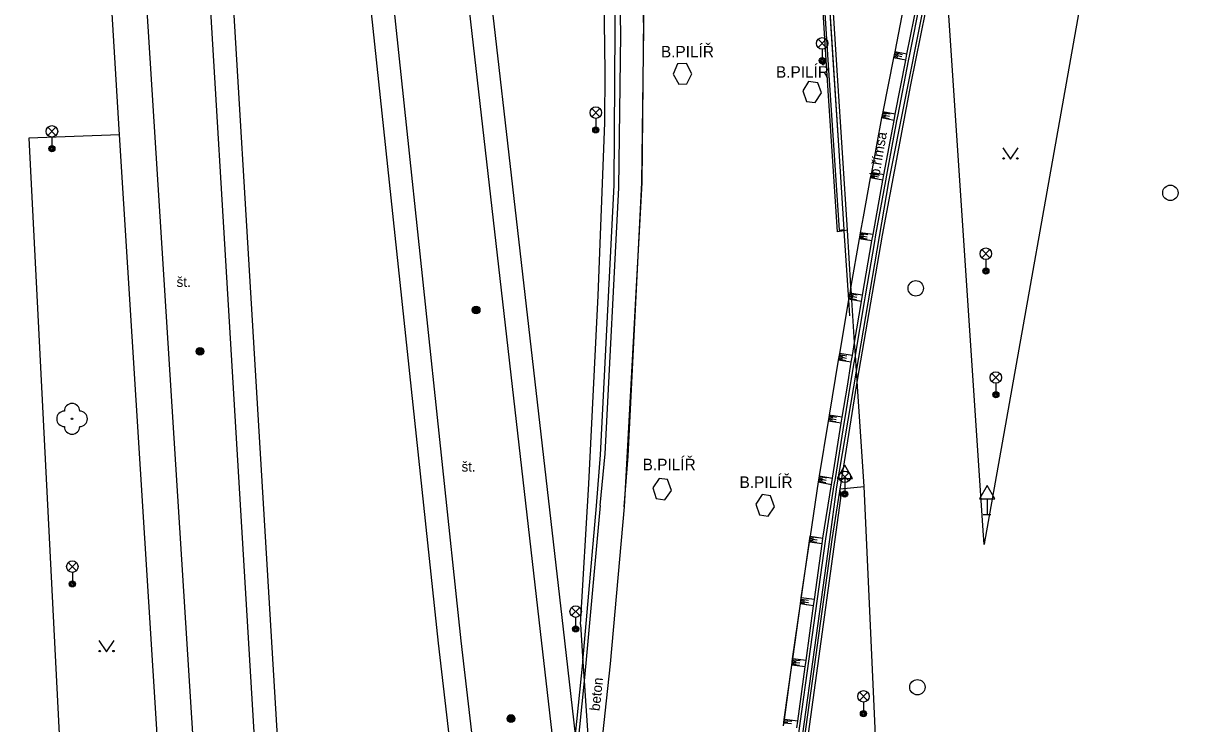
# Model space of a CAD drawing. Extents: x -599951 to -598963, y -1164095 to -1162939.
# Drawn here: x -599212.4 to -599136.9, y -1163692.1 to -1163646.4 of the extents above; entities that cross this region are included whole.
import ezdxf

# ---------------------------------------------------------------- set-up
doc = ezdxf.new("R2010")
doc.units = 0
for name, color, linetype in [('Level 10', 7, 'Continuous'), ('Level 11', 7, 'Continuous'), ('Level 13', 7, 'Continuous'), ('Level 15', 7, 'Continuous'), ('Level 22', 7, 'Continuous'), ('Level 25', 7, 'Continuous'), ('Level 27', 7, 'Continuous'), ('Level 33', 7, 'Continuous'), ('Level 34', 7, 'Continuous'), ('Level 36', 7, 'Continuous'), ('Level 40', 7, 'Continuous'), ('Level 41', 7, 'Continuous'), ('Level 9', 7, 'Continuous')]:
    doc.layers.add(name, color=color, linetype=linetype)

msp = doc.modelspace()

# ---------------------------------------------------------------- linework, layer by layer
at = {"layer": 'Level 10'}
for points in [[(-599097.7, -1163496.33), (-599101.18, -1163504.5), (-599105.65, -1163515.42), (-599108.56, -1163522.79), (-599112.67, -1163533.66), (-599115.92, -1163542.44), (-599118.17, -1163548.8), (-599119.97, -1163554.03), (-599122.34, -1163561.22), (-599124.91, -1163569.39), (-599126.83, -1163575.79), (-599128.48, -1163581.37), (-599129.72, -1163585.79), (-599133.24, -1163599), (-599135.77, -1163608.36), (-599139.28, -1163623.33), (-599143.16, -1163642.62), (-599149.778, -1163679.861), (-599149.81, -1163680.07), (-599149.87, -1163680.38)], [(-599158.77, -1163659.9), (-599159.42, -1163649.83), (-599161.31, -1163620.29)], [(-599149.87, -1163680.38), (-599149.89, -1163680.05), (-599149.909, -1163679.799), (-599152.24, -1163644.59), (-599152.53, -1163640.01)], [(-599155, -1163644.76), (-599155.67, -1163648.28)], [(-599172.15, -1163656.79), (-599172.03, -1163646.75), (-599172.06, -1163645.35)], [(-599155.76, -1163648.67), (-599156.47, -1163652.19)], [(-599155.67, -1163648.28), (-599155.76, -1163648.67)], [(-599156.55, -1163652.59), (-599157.2, -1163656.14)], [(-599156.47, -1163652.19), (-599156.55, -1163652.59)], [(-599157.28, -1163656.5), (-599157.75, -1163659.03), (-599157.93, -1163660.07)], [(-599157.2, -1163656.14), (-599157.28, -1163656.5)], [(-599173.3, -1163677.93), (-599173.05, -1163674.62), (-599172.15, -1163656.79)], [(-599158.54, -1163663.54), (-599158.77, -1163659.9)], [(-599157.93, -1163660.07), (-599158, -1163660.46)], [(-599158, -1163660.46), (-599158.54, -1163663.54)], [(-599158.62, -1163664), (-599158.69, -1163664.4)], [(-599158.54, -1163663.54), (-599158.62, -1163664)], [(-599158.51, -1163664.02), (-599158.54, -1163663.54)], [(-599158.48, -1163664.44), (-599158.51, -1163664.02)], [(-599158.7, -1163664.44), (-599159.28, -1163667.93)], [(-599158.69, -1163664.4), (-599158.7, -1163664.44)], [(-599158.3, -1163667.21), (-599158.48, -1163664.44)], [(-599158.24, -1163668.05), (-599158.3, -1163667.21)], [(-599159.37, -1163668.37), (-599159.95, -1163671.95)], [(-599159.28, -1163667.93), (-599159.37, -1163668.37)], [(-599158.17, -1163669.09), (-599158.24, -1163668.05)], [(-599158.13, -1163669.68), (-599158.17, -1163669.09)], [(-599158.13, -1163669.76), (-599158.13, -1163669.68)], [(-599157.68, -1163676.6), (-599158.13, -1163669.76)], [(-599160.02, -1163672.35), (-599160.6, -1163675.9)], [(-599159.95, -1163671.95), (-599160.02, -1163672.35)], [(-599160.6, -1163675.9), (-599160.68, -1163676.3)], [(-599162.85, -1163820.04), (-599162.62, -1163815.71), (-599158.85, -1163766.66), (-599157.06, -1163745.81), (-599155.93, -1163733.73), (-599156.18, -1163710.45), (-599156.98, -1163691.85), (-599157.68, -1163676.6)], [(-599160.68, -1163676.3), (-599161.2, -1163679.83)], [(-599161.24, -1163680.23), (-599161.2, -1163679.83)], [(-599161.77, -1163683.84), (-599161.24, -1163680.23)], [(-599162.34, -1163687.82), (-599161.83, -1163684.25)], [(-599161.83, -1163684.25), (-599161.77, -1163683.84)], [(-599162.88, -1163691.77), (-599162.39, -1163688.23)], [(-599162.39, -1163688.23), (-599162.34, -1163687.82)], [(-599162.92, -1163692.19), (-599162.88, -1163691.77)]]:
    msp.add_lwpolyline(points, dxfattribs=at)
at = {"layer": 'Level 11'}
for points in [[(-599206.17, -1163653.7), (-599209.8, -1163593.38), (-599213.54, -1163512.63), (-599213.84, -1163496.33), (-599214.13, -1163485.25)], [(-599189.36, -1163823.61), (-599189.69, -1163796.53), (-599191.33, -1163764.7), (-599192.09, -1163753.19), (-599195.83, -1163693.59), (-599200.49, -1163615.9), (-599203.73, -1163564.1), (-599205.07, -1163538.8), (-599205.4, -1163502.64)], [(-599205.4, -1163502.64), (-599201.6, -1163538.16), (-599192.85, -1163616.71), (-599185.42, -1163686.81), (-599180.49, -1163729.19)], [(-599176.47, -1163692.74), (-599177.25, -1163685.88), (-599185.21, -1163616.31), (-599194.22, -1163537.61)], [(-599176.14, -1163685.58), (-599175.61, -1163676.43), (-599174.99, -1163664.15), (-599174.55, -1163652.9), (-599174.53, -1163649.56), (-599174.7, -1163638.37), (-599174.9, -1163629.3), (-599175.26, -1163620.59), (-599175.8, -1163615.25), (-599176.49, -1163610.52), (-599177.6, -1163604.96)], [(-599175.11, -1163677.86), (-599174.84, -1163674.53), (-599173.95, -1163656.98), (-599173.87, -1163643.39), (-599174.3, -1163631.07), (-599175.13, -1163619.77), (-599176.19, -1163608.83), (-599176.71, -1163604.87)], [(-599161.5, -1163621.13), (-599159.68, -1163649.46), (-599159.35, -1163654.39)], [(-599158.99, -1163659.94), (-599159.42, -1163660.02), (-599160.1, -1163649.5), (-599161.81, -1163622.49)], [(-599161.75, -1163622.22), (-599160, -1163649.48), (-599159.31, -1163659.91)], [(-599158.24, -1163668.05), (-599157.66, -1163664.57), (-599157.59, -1163664.17), (-599156.98, -1163660.63), (-599156.91, -1163660.21), (-599156.27, -1163656.69), (-599156.2, -1163656.33), (-599155.54, -1163652.79), (-599155.46, -1163652.39), (-599154.78, -1163648.87), (-599154.71, -1163648.47), (-599154, -1163644.96), (-599153.91, -1163644.52), (-599153.19, -1163641.02), (-599153.1, -1163640.6), (-599152.62, -1163638.35)], [(-599152.53, -1163640.01), (-599153.04, -1163642.39), (-599154.67, -1163650.43), (-599156.51, -1163660.23), (-599158.13, -1163669.68)], [(-599154.9, -1163648.43), (-599154.19, -1163644.92)], [(-599154.97, -1163648.83), (-599155.76, -1163648.67)], [(-599154.9, -1163648.43), (-599155.67, -1163648.28)], [(-599155.65, -1163652.35), (-599154.97, -1163648.83)], [(-599154.97, -1163648.83), (-599154.9, -1163648.43)], [(-599169.25, -1163649.05), (-599169.83, -1163649.06), (-599170.12, -1163649.74), (-599169.75, -1163650.39), (-599169.22, -1163650.38), (-599168.9, -1163649.72), (-599169.25, -1163649.05)], [(-599160.69, -1163650.31), (-599161.29, -1163650.22), (-599161.68, -1163650.83), (-599161.43, -1163651.53), (-599160.87, -1163651.58), (-599160.46, -1163650.96), (-599160.69, -1163650.31)], [(-599155.73, -1163652.75), (-599156.55, -1163652.59)], [(-599155.65, -1163652.35), (-599156.47, -1163652.19)], [(-599156.39, -1163656.29), (-599155.73, -1163652.75)], [(-599155.73, -1163652.75), (-599155.65, -1163652.35)], [(-599206.17, -1163653.7), (-599212.07, -1163653.92), (-599206.95, -1163754.57), (-599203.73, -1163825.91)], [(-599206.17, -1163653.7), (-599212.07, -1163653.92), (-599206.95, -1163754.57), (-599203.73, -1163825.91)], [(-599197.62, -1163823.43), (-599198.47, -1163776.3), (-599199.87, -1163753.93), (-599206.17, -1163653.7)], [(-599159.35, -1163654.39), (-599158.99, -1163659.85)], [(-599156.46, -1163656.65), (-599157.28, -1163656.5)], [(-599156.39, -1163656.29), (-599157.2, -1163656.14)], [(-599156.46, -1163656.65), (-599156.39, -1163656.29)], [(-599157.1, -1163660.18), (-599156.46, -1163656.65)], [(-599159.31, -1163659.91), (-599159, -1163659.85)], [(-599159, -1163659.85), (-599158.99, -1163659.85)], [(-599158.77, -1163659.9), (-599158.99, -1163659.94)], [(-599157.1, -1163660.18), (-599157.93, -1163660.07)], [(-599157.17, -1163660.6), (-599157.1, -1163660.18)], [(-599157.17, -1163660.6), (-599158, -1163660.46)], [(-599157.78, -1163664.14), (-599157.17, -1163660.6)], [(-599158.51, -1163664.02), (-599158.62, -1163664)], [(-599157.78, -1163664.14), (-599158.51, -1163664.02)], [(-599158.48, -1163664.44), (-599158.69, -1163664.4)], [(-599157.85, -1163664.54), (-599158.48, -1163664.44)], [(-599158.3, -1163667.21), (-599157.85, -1163664.54)], [(-599157.85, -1163664.54), (-599157.78, -1163664.14)], [(-599158.44, -1163668.07), (-599158.3, -1163667.21)], [(-599160.17, -1163680.01), (-599159.62, -1163676.49), (-599159.55, -1163676.08), (-599158.98, -1163672.5), (-599158.91, -1163672.12), (-599158.58, -1163670.09), (-599158.33, -1163668.54), (-599158.25, -1163668.1), (-599158.24, -1163668.05)], [(-599158.52, -1163668.51), (-599159.37, -1163668.37)], [(-599158.44, -1163668.07), (-599159.28, -1163667.93)], [(-599159.1, -1163672.09), (-599158.77, -1163670.06), (-599158.52, -1163668.51)], [(-599158.52, -1163668.51), (-599158.44, -1163668.07)], [(-599158.13, -1163669.68), (-599158.27, -1163670.47), (-599159.78, -1163680.04)], [(-599159.17, -1163672.47), (-599160.02, -1163672.35)], [(-599159.1, -1163672.09), (-599159.95, -1163671.95)], [(-599159.17, -1163672.47), (-599159.1, -1163672.09)], [(-599159.74, -1163676.05), (-599159.17, -1163672.47)], [(-599170.48, -1163676.15), (-599171.03, -1163676.07), (-599171.44, -1163676.68), (-599171.22, -1163677.39), (-599170.65, -1163677.46), (-599170.23, -1163676.86), (-599170.48, -1163676.15)], [(-599160.6, -1163675.9), (-599159.74, -1163676.05)], [(-599159.81, -1163676.46), (-599159.74, -1163676.05)], [(-599167.61, -1163750.42), (-599167.49, -1163749.46), (-599165.73, -1163731.33), (-599162.94, -1163704.73), (-599159.2, -1163677.36), (-599159.24, -1163676.76), (-599157.68, -1163676.6)], [(-599160.68, -1163676.3), (-599159.81, -1163676.46)], [(-599160.36, -1163679.96), (-599159.81, -1163676.46)], [(-599163.77, -1163677.2), (-599164.31, -1163677.12), (-599164.72, -1163677.74), (-599164.5, -1163678.45), (-599163.93, -1163678.52), (-599163.51, -1163677.92), (-599163.77, -1163677.2)], [(-599175.99, -1163688), (-599175.11, -1163677.86)], [(-599161.2, -1163679.83), (-599160.36, -1163679.96)], [(-599160.41, -1163680.34), (-599160.36, -1163679.96)], [(-599168.09, -1163750.4), (-599167.18, -1163739.59), (-599165.19, -1163719.7), (-599162.93, -1163699.85), (-599160.17, -1163680.01)], [(-599159.78, -1163680.04), (-599162.54, -1163699.92), (-599164.82, -1163719.73), (-599166.77, -1163739.69), (-599167.68, -1163750.42)], [(-599160.41, -1163680.34), (-599161.24, -1163680.23)], [(-599160.91, -1163683.96), (-599160.41, -1163680.34)], [(-599160.97, -1163684.37), (-599161.83, -1163684.25)], [(-599160.91, -1163683.96), (-599161.77, -1163683.84)], [(-599161.46, -1163687.94), (-599160.97, -1163684.37)], [(-599160.97, -1163684.37), (-599160.91, -1163683.96)], [(-599176.14, -1163685.58), (-599175.99, -1163688)], [(-599176.47, -1163692.74), (-599176, -1163688.08), (-599175.99, -1163688)], [(-599175.99, -1163688), (-599175.91, -1163689.25)], [(-599162.38, -1163688.23), (-599162.39, -1163688.23)], [(-599161.52, -1163688.35), (-599162.38, -1163688.23)], [(-599162.32, -1163687.82), (-599162.34, -1163687.82)], [(-599161.46, -1163687.94), (-599162.32, -1163687.82)], [(-599161.52, -1163688.35), (-599161.46, -1163687.94)], [(-599162, -1163691.89), (-599161.52, -1163688.35)], [(-599175.91, -1163689.25), (-599175.31, -1163698.01)], [(-599162.86, -1163691.77), (-599162.88, -1163691.77)], [(-599162, -1163691.89), (-599162.86, -1163691.77)], [(-599162.06, -1163692.31), (-599162, -1163691.89)]]:
    msp.add_lwpolyline(points, dxfattribs=at)
at = {"layer": 'Level 13'}
for points in [[(-599191.12, -1163824.29), (-599191.19, -1163796.58), (-599192.83, -1163764.79), (-599193.59, -1163753.29), (-599197.33, -1163693.68), (-599201.99, -1163615.99), (-599205.23, -1163564.19), (-599206.57, -1163538.85), (-599206.81, -1163512.73), (-599206.44, -1163495.99), (-599204.7, -1163459.51)], [(-599191.12, -1163824.29), (-599191.19, -1163796.58), (-599192.83, -1163764.79), (-599193.59, -1163753.29), (-599197.33, -1163693.68), (-599201.99, -1163615.99), (-599205.23, -1163564.19), (-599206.57, -1163538.85), (-599206.81, -1163512.73), (-599206.44, -1163495.99), (-599204.7, -1163459.51)], [(-599177.23, -1163699.28), (-599178.74, -1163686.05), (-599186.7, -1163616.48), (-599195.66, -1163537.6), (-599200.41, -1163495.95), (-599204.7, -1163459.51)], [(-599208.62, -1163460.66), (-599210.47, -1163495.7), (-599211.19, -1163512.78), (-599210.75, -1163539.06), (-599209.44, -1163564.41), (-599206.24, -1163616.03), (-599201.34, -1163693.72), (-599197.51, -1163753.71), (-599196.88, -1163764.86), (-599195.14, -1163797.79), (-599195.48, -1163824.85)], [(-599208.62, -1163460.66), (-599210.47, -1163495.7), (-599211.19, -1163512.78), (-599210.75, -1163539.06), (-599209.44, -1163564.41), (-599206.24, -1163616.03), (-599201.34, -1163693.72), (-599197.51, -1163753.71), (-599196.88, -1163764.86), (-599195.14, -1163797.79), (-599195.48, -1163824.85)], [(-599208.62, -1163460.66), (-599204.63, -1163495.77), (-599200.11, -1163538), (-599191.36, -1163616.55), (-599183.93, -1163686.65), (-599179.8, -1163722.27)]]:
    msp.add_lwpolyline(points, dxfattribs=at)
at = {"layer": 'Level 15'}
for points in [[(-599155.75, -1163648.63), (-599155.26, -1163648.74)], [(-599155.73, -1163648.56), (-599155.49, -1163648.61)], [(-599155.72, -1163648.49), (-599155.23, -1163648.6)], [(-599155.7, -1163648.41), (-599155.46, -1163648.47)], [(-599155.68, -1163648.34), (-599155.2, -1163648.45)], [(-599156.54, -1163652.53), (-599156.05, -1163652.62)], [(-599156.52, -1163652.45), (-599156.28, -1163652.5)], [(-599156.51, -1163652.38), (-599156.02, -1163652.48)], [(-599156.49, -1163652.31), (-599156.25, -1163652.35)], [(-599156.48, -1163652.23), (-599155.99, -1163652.33)], [(-599157.27, -1163656.45), (-599156.78, -1163656.56)], [(-599157.25, -1163656.38), (-599157.01, -1163656.44)], [(-599157.24, -1163656.31), (-599156.75, -1163656.42)], [(-599157.22, -1163656.23), (-599156.98, -1163656.29)], [(-599157.2, -1163656.16), (-599156.72, -1163656.27)], [(-599157.97, -1163660.31), (-599157.73, -1163660.36)], [(-599157.96, -1163660.24), (-599157.47, -1163660.33)], [(-599157.95, -1163660.16), (-599157.7, -1163660.21)], [(-599157.93, -1163660.09), (-599157.44, -1163660.18)], [(-599157.99, -1163660.39), (-599157.49, -1163660.47)], [(-599158.64, -1163664.1), (-599158.39, -1163664.15)], [(-599158.63, -1163664.03), (-599158.13, -1163664.12)], [(-599158.68, -1163664.32), (-599158.18, -1163664.41)], [(-599158.66, -1163664.25), (-599158.42, -1163664.29)], [(-599158.65, -1163664.18), (-599158.16, -1163664.26)], [(-599159.35, -1163668.28), (-599158.86, -1163668.38)], [(-599159.34, -1163668.21), (-599159.09, -1163668.26)], [(-599159.32, -1163668.14), (-599158.83, -1163668.24)], [(-599159.31, -1163668.06), (-599159.06, -1163668.11)], [(-599159.29, -1163667.99), (-599158.8, -1163668.09)], [(-599160.01, -1163672.29), (-599159.52, -1163672.37)], [(-599160, -1163672.21), (-599159.75, -1163672.25)], [(-599159.98, -1163672.14), (-599159.49, -1163672.23)], [(-599159.97, -1163672.07), (-599159.72, -1163672.11)], [(-599159.96, -1163671.99), (-599159.47, -1163672.08)], [(-599160.65, -1163676.15), (-599160.41, -1163676.2)], [(-599160.64, -1163676.08), (-599160.15, -1163676.18)], [(-599160.62, -1163676.01), (-599160.38, -1163676.06)], [(-599160.61, -1163675.93), (-599160.12, -1163676.03)], [(-599160.67, -1163676.23), (-599160.18, -1163676.33)], [(-599161.21, -1163679.94), (-599160.97, -1163679.97)], [(-599161.2, -1163679.86), (-599160.71, -1163679.93)], [(-599161.23, -1163680.09), (-599160.99, -1163680.12)], [(-599161.23, -1163680.16), (-599160.75, -1163680.23)], [(-599161.22, -1163680.01), (-599160.73, -1163680.08)], [(-599161.83, -1163684.22), (-599161.33, -1163684.3)], [(-599161.81, -1163684.15), (-599161.57, -1163684.19)], [(-599161.8, -1163684.08), (-599161.31, -1163684.15)], [(-599161.79, -1163684), (-599161.55, -1163684.04)], [(-599161.78, -1163683.93), (-599161.29, -1163684)], [(-599162.38, -1163688.11), (-599162.13, -1163688.14)], [(-599162.38, -1163688.18), (-599161.89, -1163688.24)], [(-599162.37, -1163688.03), (-599161.87, -1163688.09)], [(-599162.36, -1163687.96), (-599162.11, -1163687.99)], [(-599162.35, -1163687.88), (-599161.85, -1163687.94)], [(-599162.9, -1163691.99), (-599162.4, -1163692.04)], [(-599162.89, -1163691.84), (-599162.39, -1163691.89)], [(-599162.89, -1163691.92), (-599162.65, -1163691.94)]]:
    msp.add_lwpolyline(points, dxfattribs=at)
at = {"layer": 'Level 22'}
msp.add_circle((-599209.25, -1163672.19), 0.05, dxfattribs=at)
for centre, start, end in [((-599209.25, -1163671.69), 0, 180), ((-599209.75, -1163672.19), 90, 270), ((-599208.75, -1163672.19), 270, 90), ((-599209.25, -1163672.69), 180, 0)]:
    msp.add_arc(centre, 0.5, start, end, dxfattribs=at)
at = {"layer": 'Level 25'}
for centre, radius in [((-599182.94, -1163665.1), 0.25), ((-599182.94, -1163665.1), 0.2), ((-599182.94, -1163665.1), 0.15), ((-599182.94, -1163665.1), 0.1), ((-599182.94, -1163665.1), 0.05), ((-599200.92, -1163667.79), 0.25), ((-599200.92, -1163667.79), 0.2), ((-599200.92, -1163667.79), 0.15), ((-599200.92, -1163667.79), 0.1), ((-599200.92, -1163667.79), 0.05), ((-599180.67, -1163691.71), 0.25), ((-599180.67, -1163691.71), 0.2), ((-599180.67, -1163691.71), 0.15), ((-599180.67, -1163691.71), 0.1), ((-599180.67, -1163691.71), 0.05)]:
    msp.add_circle(centre, radius, dxfattribs=at)
at = {"layer": 'Level 27'}
for centre in [(-599137.74, -1163657.47), (-599154.32, -1163663.69), (-599154.21, -1163689.67)]:
    msp.add_circle(centre, 0.5, dxfattribs=at)
at = {"layer": 'Level 33'}
for p, q in [((-599160.675, -1163648), (-599160.145, -1163647.47)), ((-599160.675, -1163647.47), (-599160.145, -1163648)), ((-599160.41, -1163648.11), (-599160.41, -1163648.86)), ((-599175.415, -1163652.51), (-599174.885, -1163651.98)), ((-599175.415, -1163651.98), (-599174.885, -1163652.51)), ((-599175.15, -1163652.62), (-599175.15, -1163653.37)), ((-599210.825, -1163653.73), (-599210.295, -1163653.2)), ((-599210.825, -1163653.2), (-599210.295, -1163653.73)), ((-599210.56, -1163653.84), (-599210.56, -1163654.59)), ((-599150.015, -1163661.7), (-599149.485, -1163661.17)), ((-599150.015, -1163661.17), (-599149.485, -1163661.7)), ((-599149.75, -1163661.81), (-599149.75, -1163662.56)), ((-599149.365, -1163669.76), (-599148.835, -1163669.23)), ((-599149.365, -1163669.23), (-599148.835, -1163669.76)), ((-599149.1, -1163669.87), (-599149.1, -1163670.62)), ((-599159.205, -1163676.23), (-599158.675, -1163675.7)), ((-599159.205, -1163675.7), (-599158.675, -1163676.23)), ((-599158.94, -1163676.34), (-599158.94, -1163677.09)), ((-599209.495, -1163682.08), (-599208.965, -1163681.55)), ((-599209.495, -1163681.55), (-599208.965, -1163682.08)), ((-599209.23, -1163682.19), (-599209.23, -1163682.94)), ((-599176.725, -1163685.01), (-599176.195, -1163684.48)), ((-599176.725, -1163684.48), (-599176.195, -1163685.01)), ((-599176.46, -1163685.12), (-599176.46, -1163685.87)), ((-599157.985, -1163690.53), (-599157.455, -1163690)), ((-599157.985, -1163690), (-599157.455, -1163690.53)), ((-599157.72, -1163690.64), (-599157.72, -1163691.39))]:
    msp.add_line(p, q, dxfattribs=at)
for centre, radius in [((-599160.41, -1163647.735), 0.375), ((-599160.41, -1163648.86), 0.2), ((-599160.41, -1163648.86), 0.145), ((-599160.41, -1163648.86), 0.0876), ((-599175.15, -1163652.245), 0.375), ((-599210.56, -1163653.465), 0.375), ((-599175.15, -1163653.37), 0.2), ((-599175.15, -1163653.37), 0.145), ((-599175.15, -1163653.37), 0.0876), ((-599210.56, -1163654.59), 0.2), ((-599210.56, -1163654.59), 0.145), ((-599210.56, -1163654.59), 0.0876), ((-599149.75, -1163661.435), 0.375), ((-599149.75, -1163662.56), 0.2), ((-599149.75, -1163662.56), 0.145), ((-599149.75, -1163662.56), 0.0876), ((-599149.1, -1163669.495), 0.375), ((-599149.1, -1163670.62), 0.2), ((-599149.1, -1163670.62), 0.145), ((-599149.1, -1163670.62), 0.0876), ((-599158.94, -1163675.965), 0.375), ((-599158.94, -1163677.09), 0.2), ((-599158.94, -1163677.09), 0.145), ((-599158.94, -1163677.09), 0.0876), ((-599209.23, -1163681.815), 0.375), ((-599209.23, -1163682.94), 0.2), ((-599209.23, -1163682.94), 0.145), ((-599209.23, -1163682.94), 0.0876), ((-599176.46, -1163684.745), 0.375), ((-599176.46, -1163685.87), 0.2), ((-599176.46, -1163685.87), 0.145), ((-599176.46, -1163685.87), 0.0876), ((-599157.72, -1163690.265), 0.375), ((-599157.72, -1163691.39), 0.2), ((-599157.72, -1163691.39), 0.145), ((-599157.72, -1163691.39), 0.0876)]:
    msp.add_circle(centre, radius, dxfattribs=at)
at = {"layer": 'Level 34'}
for p, q in [((-599158.94, -1163676.072), (-599158.94, -1163677.09)), ((-599149.67, -1163677.402), (-599149.67, -1163678.42)), ((-599149.92, -1163678.42), (-599149.42, -1163678.42))]:
    msp.add_line(p, q, dxfattribs=at)
for points in [[(-599159.44, -1163676.072), (-599158.44, -1163676.072), (-599158.94, -1163675.206)], [(-599150.17, -1163677.402), (-599149.17, -1163677.402), (-599149.67, -1163676.536)]]:
    msp.add_lwpolyline(points, close=True, dxfattribs=at)
at = {"layer": 'Level 36'}
for points in [[(-599148.65, -1163654.53), (-599148.15, -1163655.28), (-599147.65, -1163654.53)], [(-599207.5, -1163686.62), (-599207, -1163687.37), (-599206.5, -1163686.62)]]:
    msp.add_lwpolyline(points, dxfattribs=at)
for centre in [(-599148.6, -1163655.23), (-599147.701, -1163655.23), (-599207.45, -1163687.32), (-599206.551, -1163687.32)]:
    msp.add_circle(centre, 0.05, dxfattribs=at)
at = {"layer": 'Level 9'}
for points in [[(-599174.87, -1163677.83), (-599174.54, -1163674.48), (-599173.64, -1163657.14), (-599173.51, -1163647.14), (-599173.72, -1163636.91), (-599174.19, -1163627.77), (-599174.85, -1163619.65), (-599176.27, -1163606.34), (-599176.46, -1163604.85)], [(-599161.5, -1163621.13), (-599159.35, -1163654.39)], [(-599158.17, -1163669.09), (-599156.07, -1163656.75), (-599152.86, -1163640.61), (-599152.57, -1163639.31)], [(-599172.07, -1163645.34), (-599172.05, -1163646.02), (-599172.15, -1163656.79)], [(-599159.35, -1163654.39), (-599159, -1163659.85)], [(-599172.15, -1163656.79), (-599173.3, -1163677.93)], [(-599159, -1163659.85), (-599158.99, -1163659.94)], [(-599158.99, -1163659.94), (-599158.7, -1163664.44)], [(-599158.7, -1163664.44), (-599158.63, -1163665.48)], [(-599159.91, -1163680.04), (-599159.45, -1163676.62), (-599158.17, -1163669.09)], [(-599174.87, -1163677.83), (-599175.79, -1163688.1), (-599175.91, -1163689.25)], [(-599173.3, -1163677.93), (-599174.21, -1163688.15), (-599174.88, -1163694.38), (-599175.31, -1163698.01)], [(-599161.83, -1163684.25), (-599161.2, -1163679.83)], [(-599167.82, -1163750.41), (-599166.93, -1163739.69), (-599164.93, -1163719.76), (-599162.67, -1163699.9), (-599159.91, -1163680.04)], [(-599162.32, -1163687.82), (-599161.83, -1163684.25)], [(-599162.86, -1163691.77), (-599162.38, -1163688.23)], [(-599162.38, -1163688.23), (-599162.32, -1163687.82)], [(-599175.91, -1163689.25), (-599176.36, -1163693.74)], [(-599162.92, -1163692.19), (-599162.86, -1163691.77)]]:
    msp.add_lwpolyline(points, dxfattribs=at)

# ---------------------------------------------------------------- texts
at = {"layer": 'Level 40'}
for s, rotation, p in [('b.římsa', 80.23, (-599156.68, -1163656.42)), ('beton', 83.93, (-599174.9, -1163691.24))]:
    msp.add_text(s, height=0.65, rotation=rotation, dxfattribs=at).set_placement(p)
for p in [(-599202.44, -1163663.6), (-599183.89, -1163675.63)]:
    msp.add_text('št.', height=0.65, dxfattribs=at).set_placement(p)
at = {"layer": 'Level 41'}
for p in [(-599170.91, -1163648.65), (-599163.42, -1163649.97), (-599172.1, -1163675.54), (-599165.79, -1163676.69)]:
    msp.add_text('B.PILÍŘ', height=0.75, dxfattribs=at).set_placement(p)

doc.saveas('drawing.dxf')
